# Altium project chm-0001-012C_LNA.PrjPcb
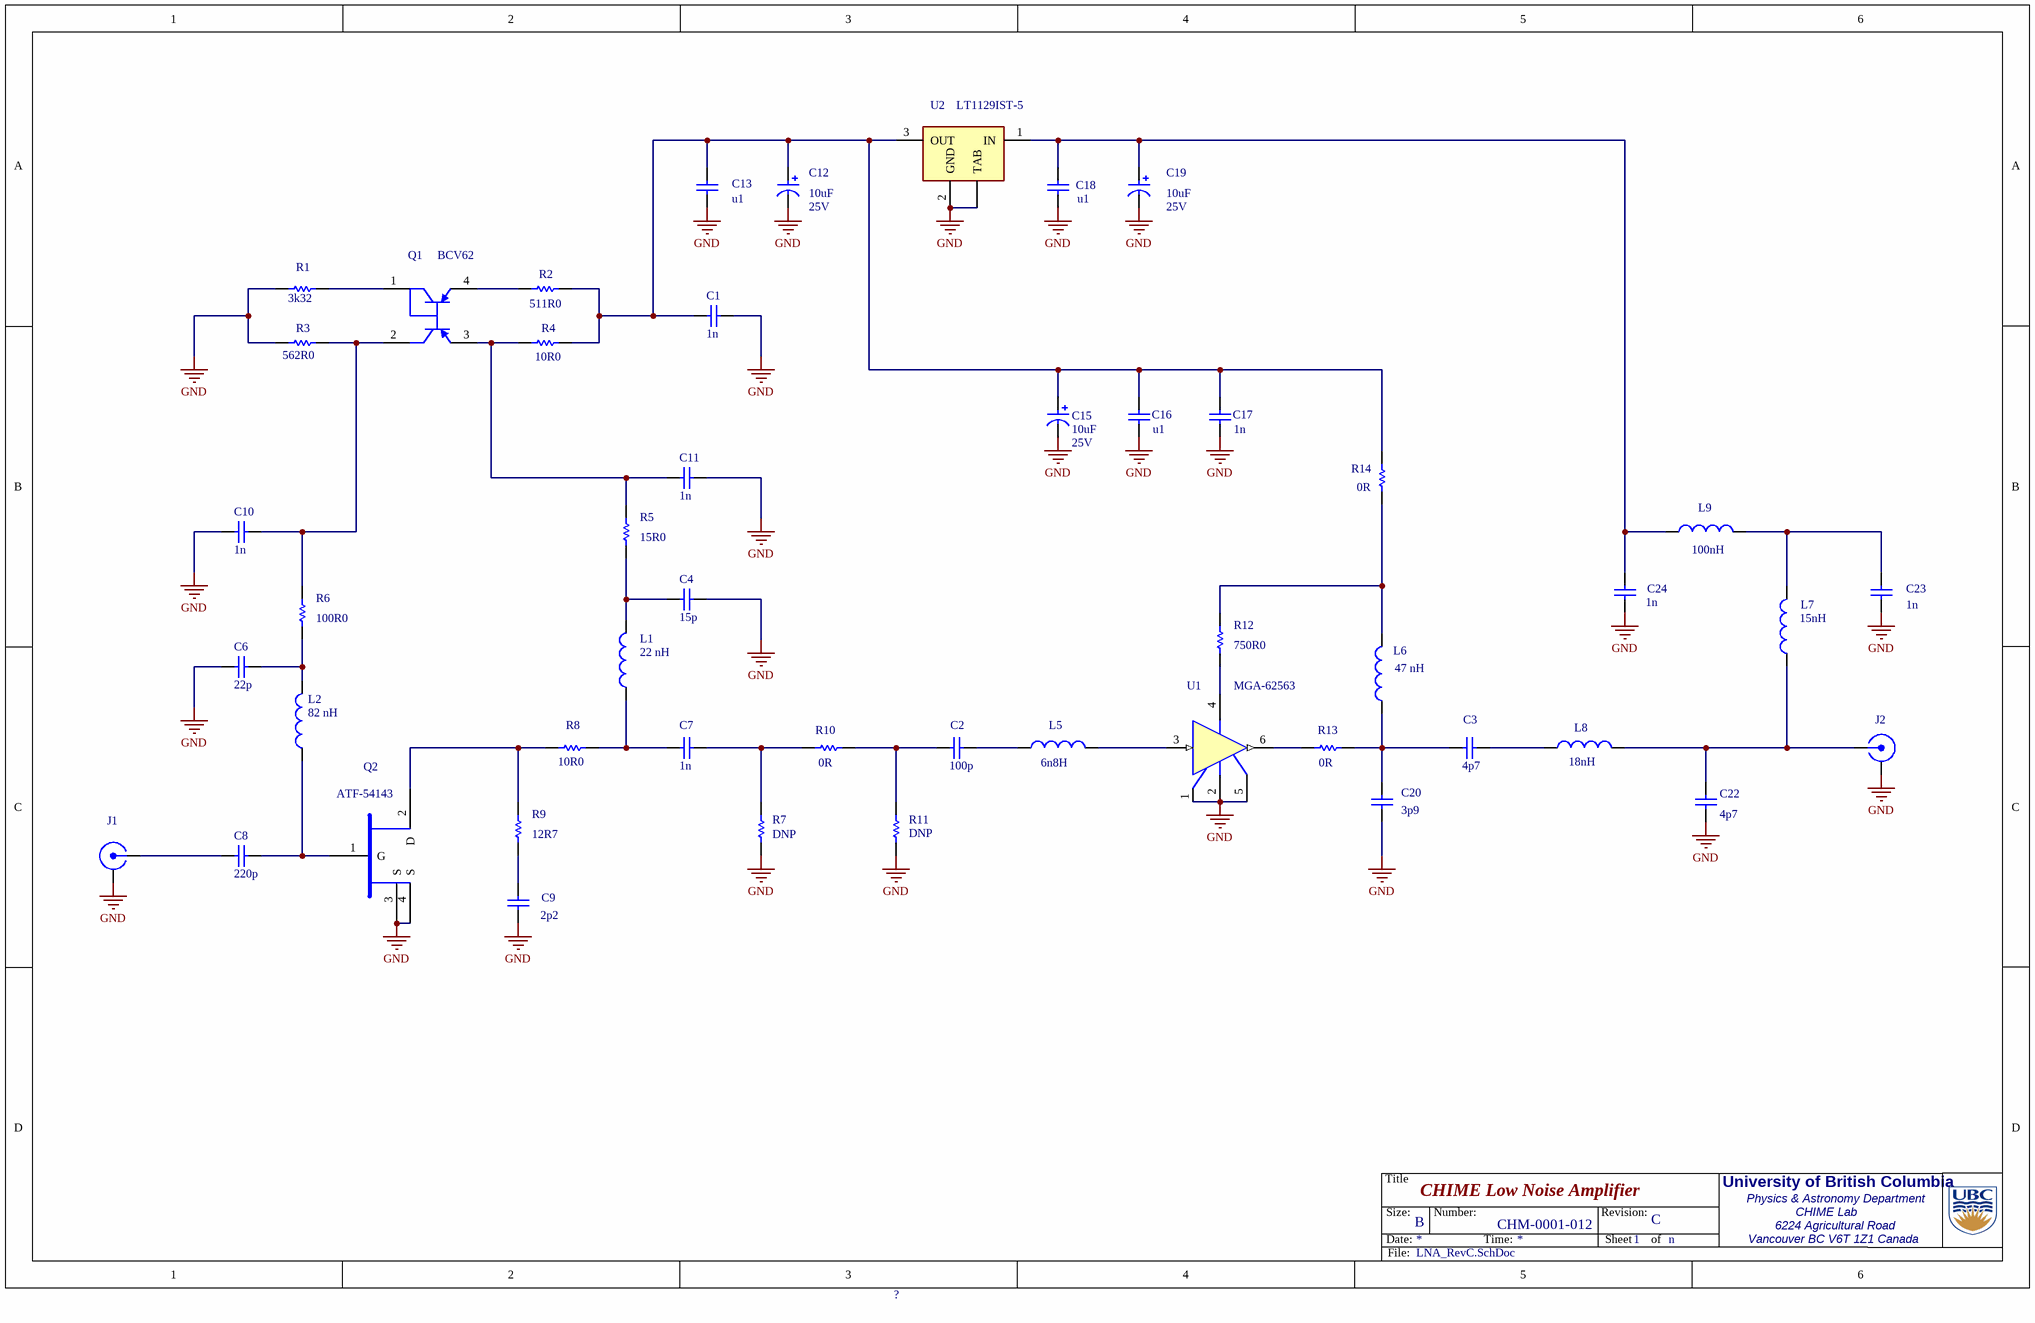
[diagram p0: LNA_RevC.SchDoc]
ASYNumber: 002902; Board#: ***; BOMTitle: CHIME Low Noise Amplifier; PO_Number: ***; Project: CHIME Project; Rev: CHM-0001-012 Rev C; Speedchart: LSCS
1 sheet, 49 parts. Net scope: global (net labels, ports and power ports of the same name join across sheets).
Board file: LNA_RevC.PcbDoc

## Sheet LNA_RevC.SchDoc: CHIME Low Noise Amplifier
size B; Organization: University of British Columbia; Address1: Physics & Astronomy Department; Address2: CHIME Lab; Address3: 6224 Agricultural Road; Address4: Vancouver BC V6T 1Z1 Canada; DocumentNumber: CHM-0001-012; Revision: C; SheetNumber: 1; SheetTotal: n

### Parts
?  UBC Logo  [UBC Logo]  (value not drawn)
C1  value 1n  [0805 LRC]  (hidden comment: C0805_1n)
C2  value 100p  [0805 LRC]  (hidden comment: C0805_100p)
C3  value 4p7  [C1608-0603]  (hidden comment: C0603_4p7)
C4  value 15p  [0805 LRC]  (hidden comment: C0805_15p)
C6  value 22p  [0805 LRC]  (hidden comment: C0805_22p)
C7  value 1n  [0805 LRC]  (hidden comment: C0805_1n)
C8  value 220p  [0805 LRC]  (hidden comment: C0805_220p)
C9  value 2p2  [0805 LRC]  (hidden comment: C0805_2p2)
C10  value 1n  [0805 LRC]  (hidden comment: C0805_1n)
C11  value 1n  [0805 LRC]  (hidden comment: C0805_1n)
C12  value 10uF  Voltage: 25V  [CC3528]  (hidden comment: Comment)
C13  value u1  [0805 LRC]  (hidden comment: C0805_u1)
C15  value 10uF  Voltage: 25V  [CC3528]  (hidden comment: Comment)
C16  value u1  [0805 LRC]  (hidden comment: C0805_u1)
C17  value 1n  [0805 LRC]  (hidden comment: C0805_1n)
C18  value u1  [0805 LRC]  (hidden comment: C0805_u1)
C19  value 10uF  Voltage: 25V  [CC3528]  (hidden comment: Comment)
C20  value 3p9  [C1608-0603]  (hidden comment: C0603_3p9)
C22  value 4p7  [C1608-0603]  (hidden comment: C0603_4p7)
C23  value 1n  [0805 LRC]  (hidden comment: C0805_1n)
C24  value 1n  [0805 LRC]  (hidden comment: C0805_1n)
J1  SMA-Edgemount  [SMA LTI]  (value not drawn)
J2  SMA-Edgemount  [SMA LTI]  (value not drawn)
L1  value 22 nH  [0805 LRC]  (hidden comment: Ind0805_22nH)
L2  value 82 nH  [0805 LRC]  (hidden comment: Ind0805_82nH)
L5  value 6n8H  [0805 LRC]  (hidden comment: Ind0805_6n8H)
L6  value 47 nH  [0805 LRC]  (hidden comment: Ind0805_47nH)
L7  value 15nH  [R0603]  (hidden comment: Ind0603_15nH)
L8  value 18nH  [R0603]  (hidden comment: Ind0603_18nH)
L9  value 100nH  [0805 LRC]  (hidden comment: Ind0805_100nH)
Q1  BCV62  [SOT143B_N]
Q2  ATF-54143  [SOT130P210X100-4AL]
R1  value 3k32  [0805 LRC]  (hidden comment: R0805_3k32)
R2  value 511R0  [0805 LRC]  (hidden comment: R0805_511R)
R3  value 562R0  [0805 LRC]  (hidden comment: R0805_562R)
R4  value 10R0  [0805 LRC]  (hidden comment: R0805_10R)
R5  value 15R0  [0805 LRC]  (hidden comment: R0805_15R)
R6  value 100R0  [0805 LRC]  (hidden comment: R0805_100R)
R7  value DNP  [0805 LRC]  (hidden comment: R0805)
R8  value 10R0  [0805 LRC]  (hidden comment: R0805_10R)
R9  value 12R7  [0805 LRC]  (hidden comment: R0805_12R7)
R10  value 0R  [0805 LRC]  (hidden comment: R0805_0R)
R11  value DNP  [0805 LRC]  (hidden comment: R0805)
R12  value 750R0  [0805 LRC]  (hidden comment: R0805_750R)
R13  value 0R  [0805 LRC]  (hidden comment: R0805_0R)
R14  value 0R  [0805 LRC]  (hidden comment: R0805_0R)
U1  MGA-62563  [SOT-363/SC-70]
U2  LT1129IST-5  [SOT-223]

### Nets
GND: C1.1 C4.2 C6.1 C9.1 C10.1 C11.1 C12.2 C13.1 C15.2 C16.1 C17.2 C18.1 C19.2 C20.1 C22.1 C23.1 C24.1 J1.2(Y) J2.2(Y) Q2.3(S) Q2.4(S) R1.1 R3.1 R7.1 R11.1 U1.1(GND) U1.2(GND) U1.5(GND) U2.2(GND) U2.4(TAB)
NetC1_2: C1.2 C12.1 C13.2 C15.1 C16.2 C17.1 R2.2 R4.2 R14.2 U2.3(OUT)
NetC2_1: C2.1 R10.2 R11.2
NetC2_2: C2.2 L5.1
NetC3_1: C3.1 C20.2 L6.1 R13.2
NetC3_2: C3.2 L8.1
NetC4_1: C4.1 L1.2 R5.1
NetC6_2: C6.2 L2.2 R6.1
NetC7_1: C7.1 R7.2 R10.1
NetC7_2: C7.2 L1.1 R8.2
NetC8_1: C8.1 J1.1(X)
NetC8_2: C8.2 L2.1 Q2.1(G)
NetC9_2: C9.2 R9.1
NetC10_2: C10.2 Q1.2(C) R3.2 R6.2
NetC11_2: C11.2 Q1.3(E) R4.1 R5.2
NetC18_2: C18.2 C19.1 C24.2 L9.1 U2.1(IN)
NetC22_2: C22.2 J2.1(X) L7.1 L8.2
NetC23_2: C23.2 L7.2 L9.2
NetL5_2: L5.2 U1.3(IN)
NetL6_2: L6.2 R12.2 R14.1
NetQ1_1: Q1.1(C) R1.2
NetQ1_4: Q1.4(E) R2.1
NetQ2_2: Q2.2(D) R8.1 R9.2
NetR12_1: R12.1 U1.4(V+)
NetR13_1: R13.1 U1.6(OUT)

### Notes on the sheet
- Title
- Size:
- Date:
- B
- Number:
- Time:
- Revision:
- Sheet
- of
- File:

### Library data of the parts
C1 C7 C10 C11 C17 C23 C24 = C0805_1n: 1nF Ceramic NPO 0805 Capacitor; Manufacturer: Cal-Chip; Part Number: GMC21CG102J100NT; Class: Passive; MCE#: 000272 CAP; Fitted: POP; Revised: 2009-8-17TF; Type: SMD
C2 = C0805_100p: 100pF Ceramic NPO 0805 Capacitor; Manufacturer: AVX; Part Number: 08055A101JAT2A; Class: Passive; MCE#: 001423 CAP; Fitted: POP; Revised: 2009-8-17TF; Type: SMD
C3 C22 = C0603_4p7: 4.7pf  +- .1pf 50V NPO(COG); Manufacturer: MuRata; Part Number: CL10C4R7BB8NNNC; Class: Passive; Fitted: POP; MCE#: 002898 CAP; SubClass: Capacitor; Type: SMD
C4 = C0805_15p: 15pF Ceramic NPO 0805 Capacitor; Manufacturer: AVX; Part Number: 08055A150JAT2A; Class: Passive; MCE#: 002583 CAP; Fitted: POP; Revised: 2009-8-17TF; Type: SMD
C6 = C0805_22p: 22pF Ceramic NPO 0805 Capacitor; Manufacturer: AVX; Part Number: 08055A2R2CAT2A; Class: Passive; MCE#: 000599 CAP; Fitted: POP; Revised: 2009-8-17TF; Type: SMD
C8 = C0805_100p: 220pF Ceramic NPO 0805 RF Capacitor; Manufacturer: Johanson; Part Number: 251R15S221JV4E; Class: Passive; MCE#: 002896 CAP; Fitted: POP; Type: SMD
C9 = C0805_2p2: 2p2 Ceramic NPO 0805 Capacitor; Manufacturer: AVX; Part Number: 08055A22JAT2A; Class: Passive; MCE#: 002585 CAP; Fitted: POP; Revised: 2009-8-17TF; Type: SMD
C12 C15 C19 = Cap Tant 10uF 25V B-Size Low ESR: Cap Tant 10uF 25V Low ESR; Manufacturer: Kemet; Type: SMD
C13 C16 C18 = C0805_u1: u1 Ceramic X7R 0805 Capacitor; Manufacturer: Johanson; Part Number: 500R15W104KV4T; Class: Passive; MCE#: 000211 CAP; Fitted: POP; Revised: 2009-8-17TF; Type: SMD
C20 = C0603_3p9: 3.9pf  +-.1pf 0603 50V NPO; Manufacturer: Samsung; Part Number: CL10C3R9BB8NNNC; Class: Passive; Fitted: POP; MCE#: 002890 CAP; SubClass: Capacitor; Type: SMD
J1 J2 = SMA LTI: SMA long edge launch connectors female; Manufacturer: LTI; Part Number: LTI-SASF55MGT
L1 = Ind0805_22nH: 22nH 0805 Inductor; Manufacturer: Murata; Part Number: LQW2BAS22NJ00L; Class: Passive; Fitted: POP; Type: SMD; MCE#: 002265 IND
L2 = Ind0805_82nH: 82nH 0805 Inductor; Manufacturer: Murata; Part Number: LQW2BAS82NJ00L; Class: Passive; Fitted: POP; Type: SMD; MCE#: 002070 IND
L5 = Ind0805_6n8H: 6n8H 0805 Inductor; Manufacturer: Murata; Part Number: LQW2BAS6N8J00L; Class: Passive; Fitted: POP; Type: SMD; MCE#: 002588 IND
L6 = Ind0805_47nH: 47nH 0805 Inductor; Manufacturer: Murata; Part Number: LQW2BAS47NJ00L; Class: Passive; Fitted: POP; Type: SMD; MCE#: 002067 IND
L7 = Ind0603_15nH: 15nH 2% 0603; Manufacturer: MuRata; Part Number: LQW18AN15NG00(D); Class: Passive; Fitted: POP; MCE#: 002885 IND; SubClass: Inductor; Type: SMD
L8 = Ind0603_15nH: 18nH 2% 0603; Manufacturer: MuRata; Part Number: LQW18AN18NG00(D); Class: Passive; Fitted: POP; MCE#: 002897 IND; SubClass: Inductor; Type: SMD
L9 = Ind0805_100nH: 100nH 0805 Inductor; Manufacturer: Murata; Part Number: LQW2BASR10J00L; Class: Passive; Fitted: POP; Type: SMD; MCE#: 002071 IND
Q1 = BCV62: PNP General-purpose Double Transistor; Manufacturer: Infineon; Part Number: BCV 62B E6327; Fitted: POP; Type: SMD; MCE#: 002293 TRA
Q2 = ATF-54143: Avagotech GaAs FET enhancement pHEMT; pin to pad: 1>3 2>1 3>2; Manufacturer: Avago Technoligies; Class: Transistor; MCE#: 002292 TRA; Fitted: POP; Type: SMD
R1 = R0805_3k32: 3k32 0805 0.1% 10ppm Resistor; Manufacturer: Generic; MCE#: 002592 RES; Class: Passive; Fitted: POP
R2 = R0805_511R: 511R 0805 0.1% 10ppm Resistor; Manufacturer: Generic; MCE#: 002593 RES; Class: Passive; Fitted: POP
R3 = R0805_562R: 562R 0805 0.1% 10ppm Resistor; Manufacturer: Generic; MCE#: 002594 RES; Class: Passive; Fitted: POP
R4 R8 = R0805_10R: 10R 0805 0.1% 10ppm Resistor; Manufacturer: Generic; MCE#: 002597 RES; Class: Passive; Fitted: POP
R5 = R0805_15R: 15R 0805 0.1% 10ppm Resistor; Manufacturer: Generic; MCE#: 002595 RES; Class: Passive; Fitted: POP
R6 = R0805_100R: 100R 0805 0.1% 10ppm Resistor; Manufacturer: Generic; MCE#: 001163 RES; Class: Passive; Fitted: POP
R7 R11 = R0805: ??? 0805 1% Resistor; Manufacturer: Generic; Class: Passive; Fitted: POP
R9 = R0805_12R7: 12R7 0805 0.1% 10ppm Resistor; Manufacturer: Generic; MCE#: 002598 RES; Class: Passive; Fitted: POP
R10 R13 R14 = R0805_0R: 0R 0805 1% Resistor; Manufacturer: Generic; MCE#: 000253 RES; Class: Passive; Fitted: POP
R12 = R0805_750R: 750R 0805 0.1% 25ppm Resistor; Manufacturer: Generic; MCE#: 002953 RES; Class: Passive; Fitted: POP
U1 = MGA-62563: Low Noise RF Amplifier; Manufacturer: Avago Technoligies; Revised: 2012-8-14TF; MCE#: 002509; Fitted: POP
U2 = LT1129IST-5: LDO +5V Regulator 700mA; Manufacturer: Linear Technology; MCE#: 000167 ICA; Fitted: POP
